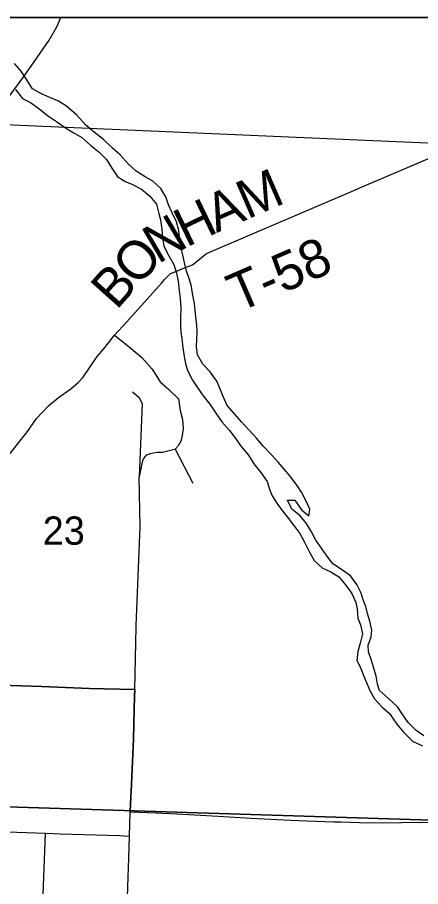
# Model space of a CAD drawing. Extents: x 0 to 34, y 0 to 22.
# Drawn here: x 4.408 to 5.004, y 19.613 to 20.9 of the extents above; entities that cross this region are included whole.
import ezdxf

# ---------------------------------------------------------------- set-up
doc = ezdxf.new("R2010")
doc.units = 0
for name, color, linetype in [('Default', 7, 'Continuous'), ('GM_X_City_Street', 7, 'Continuous'), ('GM_X_County_Road', 7, 'Continuous'), ('GM_X_Major_River', 7, 'Continuous'), ('GM_X_Section', 7, 'Continuous'), ('GM_X_Section_Text', 7, 'Continuous'), ('GM_X_State_Route', 7, 'Continuous'), ('GM_X_Township_Road', 7, 'Continuous'), ('GM_X_Township_Road_Text', 7, 'Continuous'), ('GM_X_US_Route', 7, 'Continuous'), ('SH_Data', 7, 'Continuous')]:
    doc.layers.add(name, color=color, linetype=linetype)

msp = doc.modelspace()

# ---------------------------------------------------------------- linework, layer by layer
at = {"layer": 'Default'}
msp.add_lwpolyline([(6.0871, 20.9), (2.1, 20.9), (2.1, 17.8044), (2.8305, 17.7727), (2.976, 17.7664), (3.1037, 17.7609), (3.4544, 17.7458), (3.7662, 17.7368), (3.9904, 17.7296), (4.1165, 17.7286), (4.1238, 17.7269), (4.1354, 17.7264), (4.1969, 17.7246), (4.2769, 17.7222), (4.4203, 17.718), (4.506, 17.7155), (4.6237, 17.7121), (4.6735, 17.7102), (4.763, 17.7084), (4.9045, 17.7039), (4.98, 17.7015), (5.0396, 17.6997)], dxfattribs=at)
msp.add_lwpolyline([(5.1123, 20.9), (4.1106, 20.9), (4.105, 20.7535), (5.1049, 20.7104)], close=True, dxfattribs=at)
at = {"layer": 'GM_X_City_Street'}
for points in [[(4.5838, 19.9997), (4.5897, 20.1456), (4.5878, 20.2198)], [(4.5817, 19.9046), (4.5837, 19.9978), (4.5838, 19.9997)], [(4.4305, 19.2249), (4.4317, 19.244), (4.4403, 19.4432), (4.4492, 19.6919)]]:
    msp.add_lwpolyline(points, dxfattribs=at)
at = {"layer": 'GM_X_County_Road'}
msp.add_lwpolyline([(3.9443, 19.7132), (4.0289, 19.7104), (4.1143, 19.7066), (4.1437, 19.7048), (4.2795, 19.6982), (4.4492, 19.6919), (4.4711, 19.6913), (4.5591, 19.6887), (4.5735, 19.6877)], dxfattribs=at)
at = {"layer": 'GM_X_Major_River'}
for points in [[(4.6531, 20.5457), (4.6498, 20.5606), (4.6475, 20.5747), (4.6466, 20.5846), (4.6432, 20.5972), (4.6367, 20.6107), (4.6314, 20.6226), (4.6275, 20.6344), (4.6199, 20.6464), (4.6084, 20.6574), (4.5968, 20.6641), (4.5838, 20.6725), (4.5723, 20.6827), (4.5601, 20.6963), (4.5479, 20.7069), (4.5353, 20.719), (4.522, 20.7296), (4.5086, 20.741), (4.4957, 20.755), (4.4805, 20.7683), (4.4686, 20.7759), (4.4558, 20.7815), (4.4434, 20.7868), (4.4304, 20.7944), (4.4216, 20.8075), (4.4132, 20.8203), (4.4037, 20.8319)], [(4.4049, 20.7932), (4.4155, 20.78), (4.4271, 20.774), (4.4394, 20.7649), (4.4524, 20.7547), (4.4655, 20.7456), (4.4789, 20.7365), (4.4905, 20.7297), (4.5032, 20.7221), (4.5165, 20.7104), (4.5287, 20.7002), (4.5398, 20.6896), (4.5478, 20.6765), (4.5555, 20.6649), (4.5663, 20.6574), (4.5783, 20.6525), (4.5914, 20.6457), (4.604, 20.6351), (4.6135, 20.6234), (4.6173, 20.6097), (4.6197, 20.6001), (4.6216, 20.5864), (4.6224, 20.5742), (4.6243, 20.5613), (4.6319, 20.547)], [(4.6319, 20.547), (4.6391, 20.5339), (4.6433, 20.5213), (4.6457, 20.5094), (4.6472, 20.4957), (4.6487, 20.4835), (4.6495, 20.4695), (4.6491, 20.4554), (4.6491, 20.4433), (4.6496, 20.4338), (4.6509, 20.4239), (4.6524, 20.4113), (4.6547, 20.3976), (4.6567, 20.3873), (4.6594, 20.3773), (4.667, 20.3627), (4.6736, 20.3526), (4.6827, 20.3395), (4.6926, 20.3271), (4.7024, 20.3124), (4.7105, 20.3011), (4.7215, 20.2883), (4.7296, 20.2778), (4.7391, 20.2647), (4.7497, 20.2518), (4.7577, 20.2391), (4.768, 20.2259), (4.7775, 20.2127), (4.7806, 20.2013), (4.7845, 20.1917), (4.7907, 20.182), (4.7976, 20.1723), (4.809, 20.158), (4.8167, 20.1475), (4.8258, 20.1359), (4.8327, 20.1228), (4.8395, 20.1093), (4.8467, 20.0958), (4.8586, 20.0848), (4.8713, 20.0792), (4.8833, 20.0716), (4.8932, 20.0596), (4.9027, 20.0468), (4.9084, 20.0337), (4.9104, 20.0242), (4.9116, 20.0105), (4.9155, 20.0005), (4.9185, 19.9871), (4.9147, 19.9736), (4.9113, 19.9612), (4.9102, 19.9479), (4.9152, 19.9375), (4.9188, 19.9279), (4.9237, 19.916), (4.9291, 19.9033), (4.9359, 19.891), (4.947, 19.8793), (4.9585, 19.8691), (4.9691, 19.8536), (4.979, 19.8416), (4.9923, 19.8283), (5.0073, 19.8215)], [(5.0092, 19.8362), (4.9973, 19.8445), (4.9858, 19.8558), (4.9771, 19.8686), (4.9705, 19.8787), (4.9569, 19.8916), (4.9435, 19.9033), (4.9404, 19.9129), (4.9388, 19.9247), (4.9346, 19.9377), (4.9315, 19.9477), (4.9273, 19.9607), (4.9268, 19.9702), (4.9313, 19.983), (4.9323, 19.9928), (4.9293, 20.0058), (4.9258, 20.0173), (4.9231, 20.0276), (4.9195, 20.0376), (4.9164, 20.0472), (4.9099, 20.0603), (4.9004, 20.0731), (4.8889, 20.0817), (4.8747, 20.0908), (4.8648, 20.104), (4.8579, 20.1141), (4.8495, 20.1261), (4.843, 20.1384), (4.8357, 20.1504), (4.8262, 20.162), (4.8139, 20.1719), (4.8075, 20.1849), (4.8181, 20.185), (4.8283, 20.1707), (4.8391, 20.1621), (4.8405, 20.1719), (4.8344, 20.1846), (4.8279, 20.1969), (4.8217, 20.2066), (4.8108, 20.2209), (4.8023, 20.231), (4.7935, 20.2415), (4.7846, 20.2513), (4.7714, 20.2653), (4.7622, 20.2765), (4.75, 20.2894), (4.7393, 20.3011), (4.729, 20.3131), (4.718, 20.3252), (4.7123, 20.3387), (4.7084, 20.3483), (4.703, 20.3613), (4.6928, 20.3749), (4.6821, 20.3866), (4.6745, 20.4001), (4.673, 20.4126), (4.6736, 20.4339), (4.6731, 20.4445), (4.6719, 20.4563), (4.671, 20.4662), (4.6698, 20.4761), (4.6668, 20.491), (4.6652, 20.5013), (4.6614, 20.5147), (4.6582, 20.5243), (4.6555, 20.5346), (4.6531, 20.5457)]]:
    msp.add_lwpolyline(points, dxfattribs=at)
at = {"layer": 'GM_X_Section'}
for points in [[(5.1049, 20.7104), (5.0674, 19.7096), (4.0623, 19.7415), (4.105, 20.7535)], [(4.0623, 19.7415), (5.0674, 19.7096), (5.0264, 18.7096), (4.0218, 18.7461)]]:
    msp.add_lwpolyline(points, close=True, dxfattribs=at)
at = {"layer": 'GM_X_State_Route'}
for points in [[(4.4172, 20.8125), (4.4283, 20.8279), (4.4547, 20.8661), (4.4663, 20.886), (4.4722, 20.9)], [(4.3005, 20.6534), (4.3174, 20.6721), (4.3362, 20.6971), (4.366, 20.7398), (4.3933, 20.7793), (4.4172, 20.8125)], [(4.3619, 19.9126), (4.3832, 19.9114), (4.4436, 19.9092), (4.5147, 19.9063), (4.5817, 19.9046), (4.5816, 19.9036)], [(4.5816, 19.9036), (4.5811, 19.8953), (4.5795, 19.8319), (4.5773, 19.7757), (4.5761, 19.7538)], [(4.5761, 19.7538), (4.5756, 19.7459), (4.5748, 19.7235)], [(4.5748, 19.7235), (4.6126, 19.7223), (4.6438, 19.7208), (4.7049, 19.7171), (4.7536, 19.7141), (4.7919, 19.7125), (4.8122, 19.7113), (4.8359, 19.7104), (4.8761, 19.709), (4.8861, 19.7087)], [(4.8861, 19.7087), (4.9141, 19.7079), (4.9476, 19.7074), (4.976, 19.7077), (5.0025, 19.7082), (5.029, 19.7079), (5.0731, 19.7082), (5.1248, 19.7083), (5.1888, 19.7082), (5.232, 19.7085), (5.2378, 19.7085)]]:
    msp.add_lwpolyline(points, dxfattribs=at)
at = {"layer": 'GM_X_Township_Road'}
for p, q in [((4.8408, 20.6158), (4.9091, 20.645)), ((4.9091, 20.645), (4.9146, 20.6474)), ((4.6414, 20.2608), (4.6676, 20.2105))]:
    msp.add_line(p, q, dxfattribs=at)
for points in [[(4.9146, 20.6474), (5.0151, 20.6904), (5.0527, 20.7079), (5.0738, 20.7123), (5.1072, 20.7117), (5.1357, 20.7109), (5.1908, 20.7091), (5.3011, 20.7072), (5.4133, 20.7123), (5.516, 20.7155), (5.5313, 20.7199), (5.6403, 20.8625), (5.6515, 20.8758), (5.6714, 20.8899), (5.6897, 20.9)], [(4.6502, 20.527), (4.667, 20.5337), (4.6878, 20.5503), (4.8408, 20.6158)], [(4.5326, 20.4057), (4.5372, 20.4113), (4.5517, 20.4292), (4.5698, 20.4493), (4.6208, 20.5066), (4.6261, 20.5125), (4.6345, 20.5207), (4.6474, 20.5259), (4.6502, 20.527)], [(4.5517, 20.4292), (4.5734, 20.4122), (4.592, 20.3964), (4.607, 20.379), (4.619, 20.3602), (4.6312, 20.3493), (4.6463, 20.3354), (4.6488, 20.318), (4.652, 20.3045), (4.653, 20.2907), (4.6511, 20.2778), (4.6494, 20.2724), (4.6458, 20.2655), (4.6414, 20.2608), (4.6345, 20.2585), (4.6225, 20.2557), (4.6144, 20.2559), (4.6039, 20.2538), (4.5979, 20.2511), (4.5935, 20.2452), (4.5913, 20.2368), (4.5878, 20.2198)], [(4.3798, 20.2329), (4.4228, 20.2867), (4.4363, 20.306), (4.4543, 20.3251), (4.4689, 20.3372), (4.4868, 20.35), (4.4979, 20.3592), (4.5054, 20.3674), (4.5261, 20.3977), (4.5326, 20.4057)], [(4.578, 20.3454), (4.5877, 20.3375), (4.5923, 20.3282), (4.5878, 20.2198)]]:
    msp.add_lwpolyline(points, dxfattribs=at)
at = {"layer": 'GM_X_US_Route'}
for points in [[(4.5816, 19.9036), (4.5817, 19.9046), (4.5147, 19.9063), (4.4436, 19.9092), (4.3832, 19.9114), (4.3619, 19.9126)], [(4.5761, 19.7538), (4.5773, 19.7757), (4.5795, 19.8319), (4.5811, 19.8953), (4.5816, 19.9036)], [(4.5748, 19.7235), (4.5756, 19.7459), (4.5761, 19.7538)], [(4.5632, 19.404), (4.5644, 19.4301), (4.5668, 19.4969), (4.5676, 19.5221), (4.5698, 19.5674), (4.5711, 19.6128), (4.5729, 19.6551), (4.5735, 19.6877), (4.5748, 19.7235)]]:
    msp.add_lwpolyline(points, dxfattribs=at)
at = {"layer": 'SH_Data'}
msp.add_line((2.1, 20.9), (8.9, 20.9), dxfattribs=at)

# ---------------------------------------------------------------- texts
at = {"layer": 'GM_X_Section_Text'}
msp.add_text('23', height=0.04186, rotation=0, dxfattribs=at).set_placement((4.4453, 20.1191))
at = {"layer": 'GM_X_Township_Road_Text'}
for s, height, rotation, p in [('M', 0.0568, 23.5221, (4.7481, 20.6006)), ('A', 0.0568, 23.6479, (4.7024, 20.5805)), ('H', 0.0568, 25.7651, (4.6578, 20.559)), ('N', 0.0568, 30.5211, (4.6159, 20.5342)), ('O', 0.0568, 47.2399, (4.5853, 20.5002)), ('T-58', 0.05682, 23.385, (4.7344, 20.4627)), ('B', 0.0568, 48.2618, (4.5544, 20.4656))]:
    msp.add_text(s, height=height, rotation=rotation, dxfattribs=at).set_placement(p)

doc.saveas('drawing.dxf')
